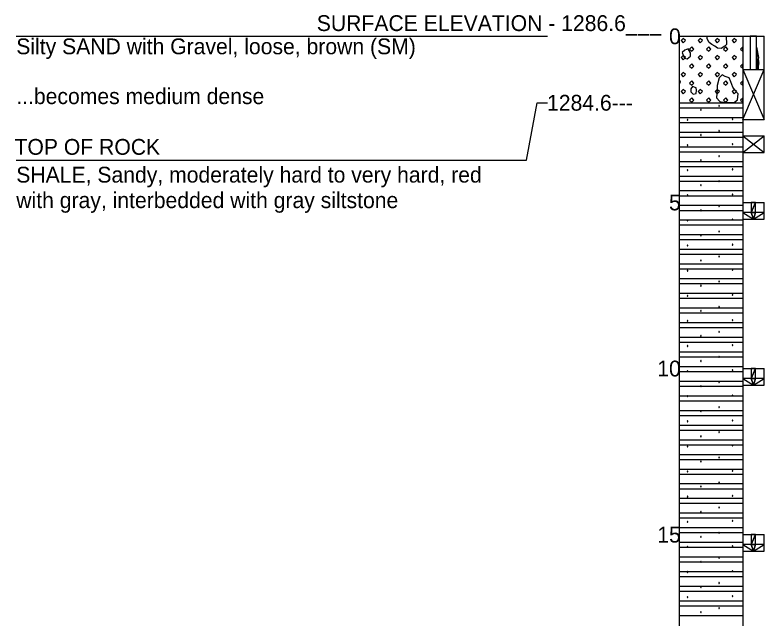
# Model space of a CAD drawing. Extents: x -2 to 138, y 24 to 58.
# Drawn here: x 54.7 to 60.57, y 44.45 to 49.18 of the extents above; entities that cross this region are included whole.
import ezdxf

# ---------------------------------------------------------------- set-up
doc = ezdxf.new("R2010")
doc.units = 0

msp = doc.modelspace()

# ---------------------------------------------------------------- linework, layer by layer
for points in [[(54.7073, 49.0098), (58.874, 49.0098)], [(59.9039, 49.0098), (59.9039, 39.8952)], [(59.9039, 49.0098), (60.4039, 49.0098)], [(59.9539, 48.9765), (59.9372, 48.9931), (59.9205, 48.9765), (59.9372, 48.9598), (59.9539, 48.9765)], [(60.0872, 48.9765), (60.0705, 48.9931), (60.0539, 48.9765), (60.0705, 48.9598), (60.0872, 48.9765)], [(60.2743, 49.0098), (60.2759, 48.9465), (60.2643, 48.9315), (60.2343, 48.9148), (60.2059, 48.9165), (60.1843, 48.9315), (60.1609, 48.9465), (60.1393, 48.9615), (60.1259, 48.9898), (60.1259, 49.0098)], [(60.2205, 48.9765), (60.2039, 48.9931), (60.1872, 48.9765), (60.2039, 48.9598), (60.2205, 48.9765)], [(60.3539, 48.9765), (60.3372, 48.9931), (60.3205, 48.9765), (60.3372, 48.9598), (60.3539, 48.9765)], [(60.4039, 49.0098), (60.5705, 49.0098)], [(60.4039, 49.0098), (60.4039, 39.8952)], [(60.5705, 48.7494), (60.5705, 49.0098)], [(60.0205, 48.9098), (60.0039, 48.9265), (59.9872, 48.9098), (60.0039, 48.8931), (60.0205, 48.9098)], [(60.1539, 48.9098), (60.1372, 48.9265), (60.1205, 48.9098), (60.1372, 48.8931), (60.1539, 48.9098)], [(60.2872, 48.9098), (60.2705, 48.9265), (60.2539, 48.9098), (60.2705, 48.8931), (60.2872, 48.9098)], [(60.3872, 48.9098), (60.4039, 48.8933), (60.4039, 48.9263), (60.3872, 48.9098)], [(59.9497, 48.9023), (59.9297, 48.884), (59.9364, 48.8623), (59.9464, 48.8373), (59.968, 48.834), (59.993, 48.854), (59.993, 48.8806), (59.9764, 48.9106), (59.9497, 48.9023)], [(59.9539, 48.8431), (59.9372, 48.8598), (59.9205, 48.8431), (59.9372, 48.8265), (59.9539, 48.8431)], [(60.0872, 48.8431), (60.0705, 48.8598), (60.0539, 48.8431), (60.0705, 48.8265), (60.0872, 48.8431)], [(60.2205, 48.8431), (60.2039, 48.8598), (60.1872, 48.8431), (60.2039, 48.8265), (60.2205, 48.8431)], [(60.3539, 48.8431), (60.3372, 48.8598), (60.3205, 48.8431), (60.3372, 48.8265), (60.3539, 48.8431)], [(60.0205, 48.7765), (60.0039, 48.7931), (59.9872, 48.7765), (60.0039, 48.7598), (60.0205, 48.7765)], [(60.1539, 48.7765), (60.1372, 48.7931), (60.1205, 48.7765), (60.1372, 48.7598), (60.1539, 48.7765)], [(60.2872, 48.7765), (60.2705, 48.7931), (60.2539, 48.7765), (60.2705, 48.7598), (60.2872, 48.7765)], [(60.3872, 48.7765), (60.4039, 48.76), (60.4039, 48.793), (60.3872, 48.7765)], [(60.4039, 48.7494), (60.5705, 48.7494)], [(60.4039, 48.7494), (60.5705, 48.3588)], [(60.4039, 48.3588), (60.5705, 48.7494)], [(60.4039, 48.7494), (60.5705, 48.7494)], [(60.5705, 48.3588), (60.5705, 48.7494)], [(59.9539, 48.7098), (59.9372, 48.7265), (59.9205, 48.7098), (59.9372, 48.6931), (59.9539, 48.7098)], [(60.0872, 48.7098), (60.0705, 48.7265), (60.0539, 48.7098), (60.0705, 48.6931), (60.0872, 48.7098)], [(60.2205, 48.7098), (60.2039, 48.7265), (60.1872, 48.7098), (60.2039, 48.6931), (60.2205, 48.7098)], [(60.2413, 48.7066), (60.218, 48.6849), (60.203, 48.6232), (60.203, 48.5932), (60.198, 48.5282), (60.223, 48.4999), (60.258, 48.4899), (60.3397, 48.4949), (60.3613, 48.5132), (60.368, 48.5582), (60.3463, 48.5832), (60.3263, 48.6116), (60.3097, 48.6532), (60.2963, 48.6832), (60.2663, 48.6949), (60.2413, 48.7066)], [(60.3539, 48.7098), (60.3372, 48.7265), (60.3205, 48.7098), (60.3372, 48.6931), (60.3539, 48.7098)], [(59.9039, 48.6702), (59.9122, 48.6536), (59.9039, 48.6319)], [(60.0205, 48.6431), (60.0039, 48.6598), (59.9872, 48.6431), (60.0039, 48.6265), (60.0205, 48.6431)], [(60.1539, 48.6431), (60.1372, 48.6598), (60.1205, 48.6431), (60.1372, 48.6265), (60.1539, 48.6431)], [(60.2872, 48.6431), (60.2705, 48.6598), (60.2539, 48.6431), (60.2705, 48.6265), (60.2872, 48.6431)], [(60.3872, 48.6431), (60.4039, 48.6266), (60.4039, 48.6597), (60.3872, 48.6431)], [(59.9539, 48.5765), (59.9372, 48.5931), (59.9205, 48.5765), (59.9372, 48.5598), (59.9539, 48.5765)], [(60.0105, 48.6173), (59.9972, 48.599), (59.9955, 48.5756), (60.0139, 48.5573), (60.0372, 48.5623), (60.0422, 48.5873), (60.0389, 48.6073), (60.0105, 48.6173)], [(60.0872, 48.5765), (60.0705, 48.5931), (60.0539, 48.5765), (60.0705, 48.5598), (60.0872, 48.5765)], [(60.2205, 48.5765), (60.2039, 48.5931), (60.1872, 48.5765), (60.2039, 48.5598), (60.2205, 48.5765)], [(60.3539, 48.5765), (60.3372, 48.5931), (60.3205, 48.5765), (60.3372, 48.5598), (60.3539, 48.5765)], [(60.0205, 48.5098), (60.0039, 48.5265), (59.9872, 48.5098), (60.0039, 48.4931), (60.0205, 48.5098)], [(60.1539, 48.5098), (60.1372, 48.5265), (60.1205, 48.5098), (60.1372, 48.4931), (60.1539, 48.5098)], [(60.2872, 48.5098), (60.2705, 48.5265), (60.2539, 48.5098), (60.2705, 48.4931), (60.2872, 48.5098)], [(60.3872, 48.5098), (60.4039, 48.4933), (60.4039, 48.5263), (60.3872, 48.5098)], [(54.7073, 48.0399), (58.7073, 48.0399), (58.7906, 48.489), (58.874, 48.489)], [(59.9039, 48.489), (60.4039, 48.489)], [(59.9039, 48.489), (60.4039, 48.489)], [(60.2215, 48.465), (60.2199, 48.4679), (60.2166, 48.4679), (60.215, 48.465), (60.2166, 48.4622), (60.2199, 48.4622), (60.2215, 48.465)], [(59.9039, 48.4496), (60.4039, 48.4496)], [(60.0789, 48.4331), (60.0773, 48.436), (60.074, 48.436), (60.0724, 48.4332), (60.074, 48.4303), (60.0773, 48.4303), (60.0789, 48.4331)], [(59.9039, 48.3742), (60.4039, 48.3742)], [(59.9743, 48.3542), (59.9726, 48.357), (59.9693, 48.357), (59.9677, 48.3542), (59.9693, 48.3513), (59.9726, 48.3513), (59.9743, 48.3542)], [(60.327, 48.3607), (60.3254, 48.3636), (60.3221, 48.3636), (60.3205, 48.3607), (60.3221, 48.3579), (60.3254, 48.3579), (60.327, 48.3607)], [(60.4039, 48.3588), (60.5705, 48.3588)], [(59.9039, 48.3348), (60.4039, 48.3348)], [(59.9039, 48.2593), (60.4039, 48.2593)], [(60.0789, 48.2363), (60.0773, 48.2392), (60.074, 48.2392), (60.0724, 48.2364), (60.074, 48.2335), (60.0773, 48.2335), (60.0789, 48.2363)], [(60.2215, 48.2682), (60.2199, 48.271), (60.2166, 48.271), (60.215, 48.2682), (60.2166, 48.2654), (60.2199, 48.2654), (60.2215, 48.2682)], [(60.4039, 48.2286), (60.5705, 48.0984)], [(60.4039, 48.0984), (60.5705, 48.2286)], [(60.4039, 48.2286), (60.5705, 48.2286)], [(60.5705, 48.0984), (60.5705, 48.2286)], [(59.9039, 48.22), (60.4039, 48.22)], [(60.327, 48.1639), (60.3254, 48.1667), (60.3221, 48.1667), (60.3205, 48.1639), (60.3221, 48.161), (60.3254, 48.161), (60.327, 48.1639)], [(59.9039, 48.1445), (60.4039, 48.1445)], [(59.9039, 48.1051), (60.4039, 48.1051)], [(59.9743, 48.1574), (59.9726, 48.1602), (59.9693, 48.1602), (59.9677, 48.1574), (59.9693, 48.1545), (59.9726, 48.1545), (59.9743, 48.1574)], [(60.2215, 48.0713), (60.2199, 48.0742), (60.2166, 48.0742), (60.215, 48.0713), (60.2166, 48.0685), (60.2199, 48.0685), (60.2215, 48.0713)], [(60.4039, 48.0984), (60.5705, 48.0984)], [(59.9039, 48.0297), (60.4039, 48.0297)], [(59.9039, 47.9903), (60.4039, 47.9903)], [(60.0789, 48.0394), (60.0773, 48.0423), (60.074, 48.0423), (60.0724, 48.0395), (60.074, 48.0366), (60.0773, 48.0366), (60.0789, 48.0394)], [(59.9743, 47.9605), (59.9726, 47.9633), (59.9693, 47.9633), (59.9677, 47.9605), (59.9693, 47.9576), (59.9726, 47.9576), (59.9743, 47.9605)], [(60.327, 47.967), (60.3254, 47.9699), (60.3221, 47.9699), (60.3205, 47.967), (60.3221, 47.9642), (60.3254, 47.9642), (60.327, 47.967)], [(59.9039, 47.9148), (60.4039, 47.9148)], [(59.9039, 47.8755), (60.4039, 47.8755)], [(60.2215, 47.8745), (60.2199, 47.8773), (60.2166, 47.8773), (60.215, 47.8745), (60.2166, 47.8717), (60.2199, 47.8717), (60.2215, 47.8745)], [(60.0789, 47.8426), (60.0773, 47.8455), (60.074, 47.8455), (60.0724, 47.8427), (60.074, 47.8398), (60.0773, 47.8398), (60.0789, 47.8426)], [(59.9039, 47.8), (60.4039, 47.8)], [(59.9039, 47.7606), (60.4039, 47.7606)], [(59.9743, 47.7637), (59.9726, 47.7665), (59.9693, 47.7665), (59.9677, 47.7637), (59.9693, 47.7608), (59.9726, 47.7608), (59.9743, 47.7637)], [(60.327, 47.7701), (60.3254, 47.773), (60.3221, 47.773), (60.3205, 47.7701), (60.3221, 47.7673), (60.3254, 47.7673), (60.327, 47.7701)], [(60.4039, 47.7077), (60.5705, 47.7077)], [(60.5705, 47.5775), (60.5705, 47.7077)], [(59.9039, 47.6852), (60.4039, 47.6852)], [(59.9039, 47.6458), (60.4039, 47.6458)], [(60.0789, 47.6457), (60.0773, 47.6486), (60.074, 47.6486), (60.0724, 47.6458), (60.074, 47.6429), (60.0773, 47.6429), (60.0789, 47.6457)], [(60.2215, 47.6776), (60.2199, 47.6805), (60.2166, 47.6805), (60.215, 47.6776), (60.2166, 47.6748), (60.2199, 47.6748), (60.2215, 47.6776)], [(60.327, 47.5733), (60.3254, 47.5762), (60.3221, 47.5762), (60.3205, 47.5733), (60.3221, 47.5705), (60.3254, 47.5705), (60.327, 47.5733)], [(60.4039, 47.5775), (60.5705, 47.5775)], [(59.9039, 47.5703), (60.4039, 47.5703)], [(59.9039, 47.531), (60.4039, 47.531)], [(59.9743, 47.5668), (59.9726, 47.5696), (59.9693, 47.5696), (59.9677, 47.5668), (59.9693, 47.5639), (59.9726, 47.5639), (59.9743, 47.5668)], [(60.2215, 47.4808), (60.2199, 47.4836), (60.2166, 47.4836), (60.215, 47.4808), (60.2166, 47.478), (60.2199, 47.478), (60.2215, 47.4808)], [(59.9039, 47.4555), (60.4039, 47.4555)], [(59.9039, 47.4161), (60.4039, 47.4161)], [(60.0789, 47.4489), (60.0773, 47.4518), (60.074, 47.4518), (60.0724, 47.449), (60.074, 47.4461), (60.0773, 47.4461), (60.0789, 47.4489)], [(59.9039, 47.3407), (60.4039, 47.3407)], [(59.9743, 47.37), (59.9726, 47.3728), (59.9693, 47.3728), (59.9677, 47.37), (59.9693, 47.3671), (59.9726, 47.3671), (59.9743, 47.37)], [(60.327, 47.3764), (60.3254, 47.3793), (60.3221, 47.3793), (60.3205, 47.3764), (60.3221, 47.3736), (60.3254, 47.3736), (60.327, 47.3764)], [(59.9039, 47.3013), (60.4039, 47.3013)], [(60.2215, 47.2839), (60.2199, 47.2868), (60.2166, 47.2868), (60.215, 47.2839), (60.2166, 47.2811), (60.2199, 47.2811), (60.2215, 47.2839)], [(59.9039, 47.2259), (60.4039, 47.2259)], [(60.0789, 47.252), (60.0773, 47.2549), (60.074, 47.2549), (60.0724, 47.2521), (60.074, 47.2492), (60.0773, 47.2492), (60.0789, 47.252)], [(59.9039, 47.1865), (60.4039, 47.1865)], [(59.9743, 47.1731), (59.9726, 47.1759), (59.9693, 47.1759), (59.9677, 47.1731), (59.9693, 47.1702), (59.9726, 47.1702), (59.9743, 47.1731)], [(60.327, 47.1796), (60.3254, 47.1825), (60.3221, 47.1825), (60.3205, 47.1796), (60.3221, 47.1768), (60.3254, 47.1768), (60.327, 47.1796)], [(59.9039, 47.111), (60.4039, 47.111)], [(59.9039, 47.0717), (60.4039, 47.0717)], [(60.0789, 47.0552), (60.0773, 47.0581), (60.074, 47.0581), (60.0724, 47.0553), (60.074, 47.0524), (60.0773, 47.0524), (60.0789, 47.0552)], [(60.2215, 47.0871), (60.2199, 47.0899), (60.2166, 47.0899), (60.215, 47.0871), (60.2166, 47.0843), (60.2199, 47.0843), (60.2215, 47.0871)], [(59.9039, 46.9962), (60.4039, 46.9962)], [(59.9039, 46.9568), (60.4039, 46.9568)], [(59.9743, 46.9763), (59.9726, 46.9791), (59.9693, 46.9791), (59.9677, 46.9763), (59.9693, 46.9734), (59.9726, 46.9734), (59.9743, 46.9763)], [(60.327, 46.9827), (60.3254, 46.9856), (60.3221, 46.9856), (60.3205, 46.9827), (60.3221, 46.9799), (60.3254, 46.9799), (60.327, 46.9827)], [(59.9039, 46.8814), (60.4039, 46.8814)], [(60.2215, 46.8902), (60.2199, 46.8931), (60.2166, 46.8931), (60.215, 46.8902), (60.2166, 46.8874), (60.2199, 46.8874), (60.2215, 46.8902)], [(59.9039, 46.842), (60.4039, 46.842)], [(60.0789, 46.8583), (60.0773, 46.8612), (60.074, 46.8612), (60.0724, 46.8584), (60.074, 46.8555), (60.0773, 46.8555), (60.0789, 46.8583)], [(59.9039, 46.7665), (60.4039, 46.7665)], [(59.9743, 46.7794), (59.9726, 46.7822), (59.9693, 46.7822), (59.9677, 46.7794), (59.9693, 46.7765), (59.9726, 46.7765), (59.9743, 46.7794)], [(60.327, 46.7859), (60.3254, 46.7888), (60.3221, 46.7888), (60.3205, 46.7859), (60.3221, 46.7831), (60.3254, 46.7831), (60.327, 46.7859)], [(59.9039, 46.7272), (60.4039, 46.7272)], [(60.2215, 46.6934), (60.2199, 46.6962), (60.2166, 46.6962), (60.215, 46.6934), (60.2166, 46.6906), (60.2199, 46.6906), (60.2215, 46.6934)], [(59.9039, 46.6517), (60.4039, 46.6517)], [(60.0789, 46.6615), (60.0773, 46.6644), (60.074, 46.6644), (60.0724, 46.6616), (60.074, 46.6587), (60.0773, 46.6587), (60.0789, 46.6615)], [(59.9039, 46.6123), (60.4039, 46.6123)], [(59.9743, 46.5826), (59.9726, 46.5854), (59.9693, 46.5854), (59.9677, 46.5826), (59.9693, 46.5797), (59.9726, 46.5797), (59.9743, 46.5826)], [(60.327, 46.589), (60.3254, 46.5919), (60.3221, 46.5919), (60.3205, 46.589), (60.3221, 46.5862), (60.3254, 46.5862), (60.327, 46.589)], [(59.9039, 46.5369), (60.4039, 46.5369)], [(59.9039, 46.4975), (60.4039, 46.4975)], [(60.0789, 46.4646), (60.0773, 46.4675), (60.074, 46.4675), (60.0724, 46.4647), (60.074, 46.4618), (60.0773, 46.4618), (60.0789, 46.4646)], [(60.2215, 46.4965), (60.2199, 46.4993), (60.2166, 46.4993), (60.215, 46.4965), (60.2166, 46.4937), (60.2199, 46.4937), (60.2215, 46.4965)], [(59.9039, 46.4221), (60.4039, 46.4221)], [(60.4039, 46.4056), (60.5705, 46.4056)], [(60.5705, 46.2754), (60.5705, 46.4056)], [(59.9039, 46.3827), (60.4039, 46.3827)], [(59.9743, 46.3857), (59.9726, 46.3885), (59.9693, 46.3885), (59.9677, 46.3857), (59.9693, 46.3828), (59.9726, 46.3828), (59.9743, 46.3857)], [(60.327, 46.3922), (60.3254, 46.3951), (60.3221, 46.3951), (60.3205, 46.3922), (60.3221, 46.3894), (60.3254, 46.3894), (60.327, 46.3922)], [(59.9039, 46.3072), (60.4039, 46.3072)], [(60.2215, 46.2997), (60.2199, 46.3025), (60.2166, 46.3025), (60.215, 46.2997), (60.2166, 46.2969), (60.2199, 46.2969), (60.2215, 46.2997)], [(59.9039, 46.2679), (60.4039, 46.2679)], [(60.0789, 46.2678), (60.0773, 46.2707), (60.074, 46.2707), (60.0724, 46.2679), (60.074, 46.265), (60.0773, 46.265), (60.0789, 46.2678)], [(60.4039, 46.2754), (60.5705, 46.2754)], [(59.9039, 46.1924), (60.4039, 46.1924)], [(59.9743, 46.1889), (59.9726, 46.1917), (59.9693, 46.1917), (59.9677, 46.1889), (59.9693, 46.186), (59.9726, 46.186), (59.9743, 46.1889)], [(60.327, 46.1953), (60.3254, 46.1982), (60.3221, 46.1982), (60.3205, 46.1953), (60.3221, 46.1925), (60.3254, 46.1925), (60.327, 46.1953)], [(59.9039, 46.153), (60.4039, 46.153)], [(60.2215, 46.1028), (60.2199, 46.1056), (60.2166, 46.1056), (60.215, 46.1028), (60.2166, 46.1), (60.2199, 46.1), (60.2215, 46.1028)], [(59.9039, 46.0776), (60.4039, 46.0776)], [(60.0789, 46.0709), (60.0773, 46.0738), (60.074, 46.0738), (60.0724, 46.071), (60.074, 46.0681), (60.0773, 46.0681), (60.0789, 46.0709)], [(59.9039, 46.0382), (60.4039, 46.0382)], [(59.9743, 45.992), (59.9726, 45.9948), (59.9693, 45.9948), (59.9677, 45.992), (59.9693, 45.9891), (59.9726, 45.9891), (59.9743, 45.992)], [(60.327, 45.9985), (60.3254, 46.0014), (60.3221, 46.0014), (60.3205, 45.9985), (60.3221, 45.9957), (60.3254, 45.9957), (60.327, 45.9985)], [(59.9039, 45.9627), (60.4039, 45.9627)], [(59.9039, 45.9234), (60.4039, 45.9234)], [(60.0789, 45.8741), (60.0773, 45.877), (60.074, 45.877), (60.0724, 45.8742), (60.074, 45.8713), (60.0773, 45.8713), (60.0789, 45.8741)], [(60.2215, 45.906), (60.2199, 45.9088), (60.2166, 45.9088), (60.215, 45.906), (60.2166, 45.9032), (60.2199, 45.9032), (60.2215, 45.906)], [(59.9039, 45.8479), (60.4039, 45.8479)], [(59.9039, 45.8085), (60.4039, 45.8085)], [(59.9743, 45.7951), (59.9726, 45.798), (59.9693, 45.798), (59.9677, 45.7951), (59.9693, 45.7923), (59.9726, 45.7923), (59.9743, 45.7951)], [(60.327, 45.8016), (60.3254, 45.8045), (60.3221, 45.8045), (60.3205, 45.8016), (60.3221, 45.7988), (60.3254, 45.7988), (60.327, 45.8016)], [(59.9039, 45.7331), (60.4039, 45.7331)], [(60.2215, 45.7091), (60.2199, 45.7119), (60.2166, 45.7119), (60.215, 45.7091), (60.2166, 45.7063), (60.2199, 45.7063), (60.2215, 45.7091)], [(59.9039, 45.6937), (60.4039, 45.6937)], [(60.0789, 45.6772), (60.0773, 45.6801), (60.074, 45.6801), (60.0724, 45.6773), (60.074, 45.6744), (60.0773, 45.6744), (60.0789, 45.6772)], [(59.9039, 45.6182), (60.4039, 45.6182)], [(59.9039, 45.5789), (60.4039, 45.5789)], [(59.9743, 45.5983), (59.9726, 45.6011), (59.9693, 45.6011), (59.9677, 45.5983), (59.9693, 45.5954), (59.9726, 45.5954), (59.9743, 45.5983)], [(60.327, 45.6048), (60.3254, 45.6077), (60.3221, 45.6077), (60.3205, 45.6048), (60.3221, 45.602), (60.3254, 45.602), (60.327, 45.6048)], [(59.9039, 45.5034), (60.4039, 45.5034)], [(59.9039, 45.464), (60.4039, 45.464)], [(60.0789, 45.4804), (60.0773, 45.4833), (60.074, 45.4833), (60.0724, 45.4805), (60.074, 45.4776), (60.0773, 45.4776), (60.0789, 45.4804)], [(60.2215, 45.5123), (60.2199, 45.5151), (60.2166, 45.5151), (60.215, 45.5123), (60.2166, 45.5095), (60.2199, 45.5095), (60.2215, 45.5123)], [(59.9743, 45.4014), (59.9726, 45.4043), (59.9693, 45.4043), (59.9677, 45.4014), (59.9693, 45.3986), (59.9726, 45.3986), (59.9743, 45.4014)], [(60.327, 45.4079), (60.3254, 45.4108), (60.3221, 45.4108), (60.3205, 45.4079), (60.3221, 45.4051), (60.3254, 45.4051), (60.327, 45.4079)], [(59.9039, 45.3886), (60.4039, 45.3886)], [(59.9039, 45.3492), (60.4039, 45.3492)], [(60.0789, 45.2835), (60.0773, 45.2864), (60.074, 45.2864), (60.0724, 45.2836), (60.074, 45.2807), (60.0773, 45.2807), (60.0789, 45.2835)], [(60.2215, 45.3154), (60.2199, 45.3182), (60.2166, 45.3182), (60.215, 45.3154), (60.2166, 45.3126), (60.2199, 45.3126), (60.2215, 45.3154)], [(59.9039, 45.2738), (60.4039, 45.2738)], [(59.9039, 45.2344), (60.4039, 45.2344)], [(59.9743, 45.2046), (59.9726, 45.2074), (59.9693, 45.2074), (59.9677, 45.2046), (59.9693, 45.2017), (59.9726, 45.2017), (59.9743, 45.2046)], [(60.327, 45.2111), (60.3254, 45.214), (60.3221, 45.214), (60.3205, 45.2111), (60.3221, 45.2083), (60.3254, 45.2083), (60.327, 45.2111)], [(59.9039, 45.1589), (60.4039, 45.1589)], [(59.9039, 45.1196), (60.4039, 45.1196)], [(60.2215, 45.1186), (60.2199, 45.1214), (60.2166, 45.1214), (60.215, 45.1186), (60.2166, 45.1158), (60.2199, 45.1158), (60.2215, 45.1186)], [(60.0789, 45.0867), (60.0773, 45.0896), (60.074, 45.0896), (60.0724, 45.0868), (60.074, 45.0839), (60.0773, 45.0839), (60.0789, 45.0867)], [(60.4039, 45.1036), (60.5705, 45.1036)], [(60.5705, 44.9734), (60.5705, 45.1036)], [(59.9039, 45.0441), (60.4039, 45.0441)], [(59.9039, 45.0047), (60.4039, 45.0047)], [(59.9743, 45.0077), (59.9726, 45.0106), (59.9693, 45.0106), (59.9677, 45.0077), (59.9693, 45.0049), (59.9726, 45.0049), (59.9743, 45.0077)], [(60.327, 45.0142), (60.3254, 45.0171), (60.3221, 45.0171), (60.3205, 45.0142), (60.3221, 45.0114), (60.3254, 45.0114), (60.327, 45.0142)], [(60.4039, 44.9734), (60.5705, 44.9734)], [(59.9039, 44.9293), (60.4039, 44.9293)], [(59.9039, 44.8899), (60.4039, 44.8899)], [(60.0789, 44.8898), (60.0773, 44.8927), (60.074, 44.8927), (60.0724, 44.8899), (60.074, 44.887), (60.0773, 44.887), (60.0789, 44.8898)], [(60.2215, 44.9217), (60.2199, 44.9245), (60.2166, 44.9245), (60.215, 44.9217), (60.2166, 44.9189), (60.2199, 44.9189), (60.2215, 44.9217)], [(59.9039, 44.8144), (60.4039, 44.8144)], [(59.9743, 44.8109), (59.9726, 44.8137), (59.9693, 44.8137), (59.9677, 44.8109), (59.9693, 44.808), (59.9726, 44.808), (59.9743, 44.8109)], [(60.327, 44.8174), (60.3254, 44.8203), (60.3221, 44.8203), (60.3205, 44.8174), (60.3221, 44.8146), (60.3254, 44.8146), (60.327, 44.8174)], [(59.9039, 44.7751), (60.4039, 44.7751)], [(59.9039, 44.6996), (60.4039, 44.6996)], [(60.2215, 44.7249), (60.2199, 44.7277), (60.2166, 44.7277), (60.215, 44.7249), (60.2166, 44.7221), (60.2199, 44.7221), (60.2215, 44.7249)], [(59.9039, 44.6602), (60.4039, 44.6602)], [(60.0789, 44.693), (60.0773, 44.6959), (60.074, 44.6959), (60.0724, 44.6931), (60.074, 44.6902), (60.0773, 44.6902), (60.0789, 44.693)], [(59.9039, 44.5848), (60.4039, 44.5848)], [(59.9743, 44.614), (59.9726, 44.6169), (59.9693, 44.6169), (59.9677, 44.614), (59.9693, 44.6112), (59.9726, 44.6112), (59.9743, 44.614)], [(60.327, 44.6205), (60.3254, 44.6234), (60.3221, 44.6234), (60.3205, 44.6205), (60.3221, 44.6177), (60.3254, 44.6177), (60.327, 44.6205)], [(59.9039, 44.5454), (60.4039, 44.5454)], [(60.2215, 44.528), (60.2199, 44.5308), (60.2166, 44.5308), (60.215, 44.528), (60.2166, 44.5252), (60.2199, 44.5252), (60.2215, 44.528)], [(59.9039, 44.47), (60.4039, 44.47)], [(60.0789, 44.4961), (60.0773, 44.499), (60.074, 44.499), (60.0724, 44.4962), (60.074, 44.4933), (60.0773, 44.4933), (60.0789, 44.4961)]]:
    msp.add_lwpolyline(points)
for points in [[(60.4622, 49.0098), (60.4622, 48.7494), (60.5122, 48.7494), (60.5122, 49.0098)], [(60.5269, 48.8431), (60.5209, 48.8848), (60.5122, 48.9248), (60.5269, 48.8431)], [(60.5122, 48.9248), (60.5122, 48.7494), (60.5269, 48.8431), (60.5122, 48.9248)], [(60.5122, 48.7494), (60.5289, 48.8015), (60.5269, 48.8431), (60.5122, 48.7494)], [(60.5122, 48.7494), (60.5269, 48.7598), (60.5289, 48.8015), (60.5122, 48.7494)], [(60.5122, 48.7494), (60.5254, 48.7494), (60.5269, 48.7598), (60.5122, 48.7494)], [(60.4705, 47.6296), (60.5039, 47.6296), (60.5039, 47.7077), (60.4705, 47.6296)], [(60.4705, 47.6296), (60.5039, 47.7077), (60.4705, 47.7077), (60.4705, 47.6296)], [(60.4705, 47.6296), (60.4039, 47.6296), (60.4872, 47.5775), (60.4705, 47.6296)], [(60.4705, 47.6296), (60.4872, 47.5775), (60.5039, 47.6296), (60.4705, 47.6296)], [(60.4872, 47.5775), (60.5705, 47.6296), (60.5039, 47.6296), (60.4872, 47.5775)], [(60.4705, 46.3275), (60.5039, 46.3275), (60.5039, 46.4056), (60.4705, 46.3275)], [(60.4705, 46.3275), (60.5039, 46.4056), (60.4705, 46.4056), (60.4705, 46.3275)], [(60.4705, 46.3275), (60.4039, 46.3275), (60.4872, 46.2754), (60.4705, 46.3275)], [(60.4705, 46.3275), (60.4872, 46.2754), (60.5039, 46.3275), (60.4705, 46.3275)], [(60.4872, 46.2754), (60.5705, 46.3275), (60.5039, 46.3275), (60.4872, 46.2754)], [(60.4705, 45.0254), (60.5039, 45.0254), (60.5039, 45.1036), (60.4705, 45.0254)], [(60.4705, 45.0254), (60.5039, 45.1036), (60.4705, 45.1036), (60.4705, 45.0254)], [(60.4705, 45.0254), (60.4039, 45.0254), (60.4872, 44.9734), (60.4705, 45.0254)], [(60.4705, 45.0254), (60.4872, 44.9734), (60.5039, 45.0254), (60.4705, 45.0254)], [(60.4872, 44.9734), (60.5705, 45.0254), (60.5039, 45.0254), (60.4872, 44.9734)]]:
    msp.add_lwpolyline(points, close=True)

# ---------------------------------------------------------------- texts
for s, p in [('SURFACE ELEVATION - 1286.6___', (57.0636, 49.0511)), ('0', (59.8256, 48.9478)), ('Silty SAND with Gravel, loose, brown (SM)', (54.7073, 48.8691)), ('...becomes medium dense', (54.7073, 48.4785)), ('1284.6---', (58.8691, 48.427)), ('TOP OF ROCK', (54.6935, 48.0812)), ('SHALE, Sandy, moderately hard to very hard, red', (54.7073, 47.8632)), ('with gray, interbedded with gray siltstone', (54.7073, 47.6632)), ('5', (59.8256, 47.6457)), ('10', (59.7335, 46.3436)), ('15', (59.7335, 45.0416))]:
    msp.add_text(s, height=0.124).set_placement(p)

doc.saveas('drawing.dxf')
